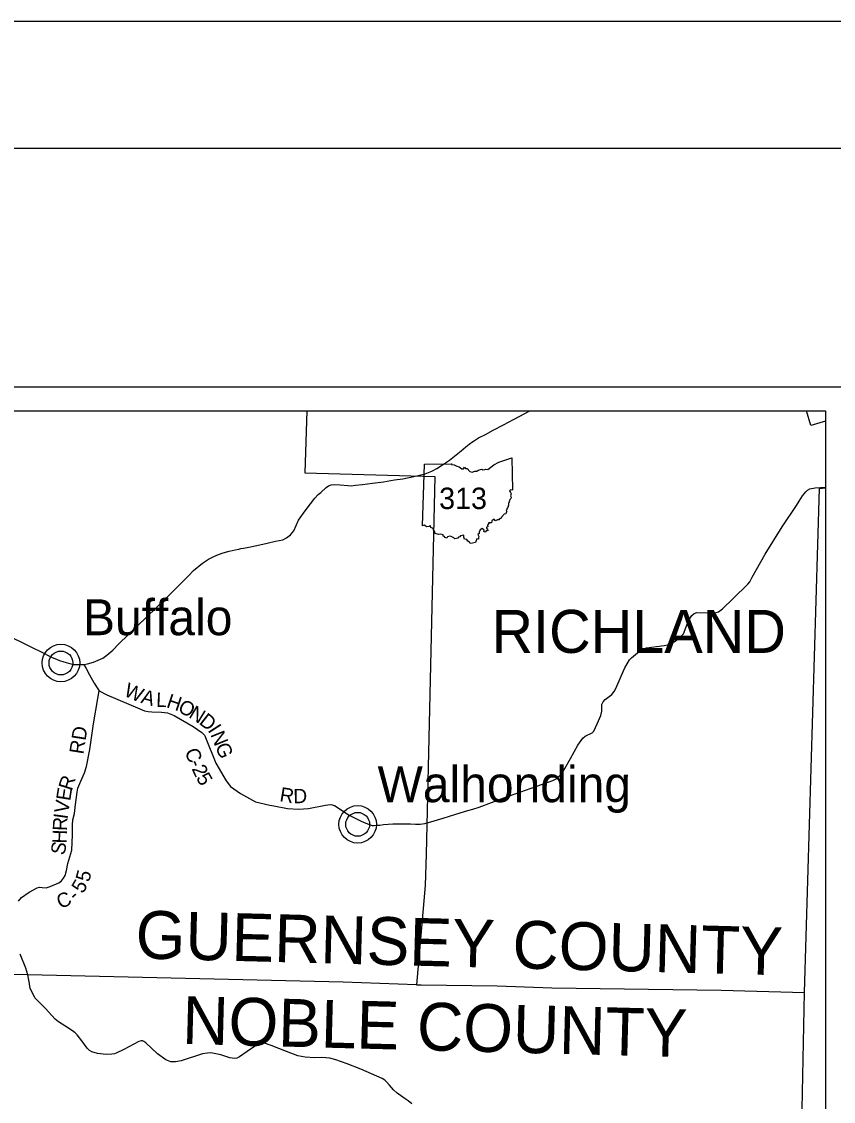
# Model space of a CAD drawing. Extents: x 0 to 34, y 0 to 22.
# Drawn here: x 27.522 to 30.728, y 17.734 to 22 of the extents above; entities that cross this region are included whole.
import ezdxf

# ---------------------------------------------------------------- set-up
doc = ezdxf.new("R2010")
doc.units = 0
for name, color, linetype in [('Default', 7, 'Continuous'), ('GM_X_Corporation', 7, 'Continuous'), ('GM_X_County_Road_Text', 7, 'Continuous'), ('GM_X_State_Route', 7, 'Continuous'), ('GM_X_Township', 7, 'Continuous'), ('GM_X_Township_Text', 7, 'Continuous'), ('GM_X_Unincorporated', 7, 'Continuous'), ('GM_X_Unincorporated_Text', 7, 'Continuous'), ('SH_Border', 7, 'Continuous'), ('SH_Cut_Line', 7, 'Continuous')]:
    doc.layers.add(name, color=color, linetype=linetype)

msp = doc.modelspace()

# ---------------------------------------------------------------- linework, layer by layer
at = {"layer": 'Default'}
for p, q in [((19.8526, 20.4625), (30.697, 20.4625)), ((30.697, 20.4625), (30.697, 9.6182)), ((29.1053, 20.0074), (29.1131, 20.2514))]:
    msp.add_line(p, q, dxfattribs=at)
msp.add_lwpolyline([(19.7581, 20.557), (30.7915, 20.557), (30.7915, 9.5237), (19.7581, 9.5237)], close=True, dxfattribs=at)
for points in [[(29.1131, 20.2514), (29.2213, 20.253), (29.2197, 20.25), (29.2298, 20.2494), (29.2407, 20.2442), (29.2499, 20.2409), (29.261, 20.2332), (29.2678, 20.2332), (29.2706, 20.2396), (29.2757, 20.2347), (29.2819, 20.2338), (29.2924, 20.2221), (29.3012, 20.2196), (29.3116, 20.2236), (29.3193, 20.2243), (29.325, 20.2282), (29.3399, 20.2316), (29.3441, 20.2296), (29.3519, 20.23), (29.3559, 20.2315), (29.3628, 20.2302), (29.3747, 20.2391), (29.3872, 20.2495), (29.4063, 20.2594), (29.4348, 20.2687), (29.4574, 20.2771), (29.4607, 20.1504)], [(29.3034, 18.8884), (29.3285, 18.8962), (29.4266, 18.9332), (29.6197, 19.0014), (29.6357, 19.0103), (29.6547, 19.0287), (29.6678, 19.049), (29.69, 19.0889), (29.7185, 19.1412), (29.7384, 19.1686), (29.7483, 19.1768), (29.7753, 19.1898), (29.7814, 19.197), (29.7956, 19.2263), (29.8092, 19.2591), (29.8139, 19.2757), (29.8133, 19.2931), (29.8141, 19.3015), (29.8187, 19.3128), (29.8271, 19.3214), (29.8431, 19.3333), (29.853, 19.3419), (29.8618, 19.3532), (29.8684, 19.3656), (29.89, 19.4139), (29.9046, 19.4463), (29.9223, 19.4779), (29.9303, 19.4865), (29.9616, 19.5131), (29.973, 19.5201), (29.9904, 19.5256), (30.029, 19.5306), (30.06, 19.5355), (30.0748, 19.5384), (30.0998, 19.5499), (30.1207, 19.5648), (30.1356, 19.5813), (30.1468, 19.6085), (30.1558, 19.6322), (30.164, 19.6452), (30.1692, 19.6533), (30.1776, 19.6619), (30.1882, 19.6652), (30.2588, 19.6638), (30.2744, 19.6678), (30.2896, 19.6801), (30.3323, 19.7206), (30.3906, 19.7775), (30.3983, 19.7869), (30.4071, 19.8054), (30.459, 19.8957), (30.5261, 20.0037), (30.5817, 20.0885), (30.5923, 20.1057), (30.6062, 20.1261), (30.6186, 20.1427), (30.6253, 20.1494), (30.6347, 20.1546), (30.6566, 20.1575), (30.697, 20.1605)], [(29.4607, 20.1504), (29.4574, 20.1487), (29.4522, 20.1495), (29.4487, 20.146), (29.453, 20.14), (29.455, 20.1338), (29.4532, 20.1269), (29.455, 20.1212), (29.4538, 20.1164), (29.4506, 20.1116), (29.4494, 20.1072), (29.4467, 20.1024), (29.4469, 20.0997), (29.4443, 20.0977), (29.4447, 20.0897), (29.4434, 20.0853), (29.4439, 20.0815), (29.4395, 20.0805), (29.4405, 20.0774), (29.4378, 20.075), (29.4384, 20.0708), (29.4353, 20.0681), (29.4383, 20.0629), (29.4359, 20.0612), (29.4339, 20.0547), (29.4284, 20.0534), (29.4174, 20.0416), (29.4135, 20.0371), (29.4092, 20.036), (29.4067, 20.0314), (29.4014, 20.0314), (29.3932, 20.0282), (29.388, 20.0337), (29.3788, 20.0271), (29.3777, 20.0195), (29.3662, 20.0197), (29.3666, 20.0159), (29.364, 20.0148), (29.3616, 20.0109), (29.363, 20.0041), (29.3575, 20.0023), (29.3582, 19.9984), (29.3617, 19.996), (29.3632, 19.9883), (29.3574, 19.9899), (29.3527, 19.9835), (29.3478, 19.985), (29.3494, 19.9904), (29.3411, 19.997), (29.3334, 19.9917), (29.3293, 19.9833), (29.3292, 19.9777), (29.3234, 19.9743), (29.3272, 19.9664), (29.3264, 19.9609), (29.3266, 19.9557), (29.3193, 19.9559), (29.3149, 19.9419)], [(29.3149, 19.9419), (29.3023, 19.9392), (29.2936, 19.9376), (29.2904, 19.944), (29.2842, 19.9474), (29.2801, 19.9537), (29.2711, 19.9546), (29.269, 19.9634), (29.268, 19.9705), (29.2557, 19.9688), (29.2523, 19.9644), (29.2479, 19.9633), (29.2454, 19.9588), (29.2394, 19.9585), (29.233, 19.9564), (29.2288, 19.9607), (29.2184, 19.9651), (29.2137, 19.9673), (29.2038, 19.9638), (29.2018, 19.9597), (29.194, 19.9615), (29.1921, 19.9661), (29.1874, 19.9675), (29.1863, 19.9723), (29.1762, 19.975), (29.1684, 19.9739), (29.1548, 19.9778), (29.1539, 19.9842), (29.1493, 19.992), (29.1469, 19.9974), (29.1383, 20.0015), (29.1365, 20.008), (29.1338, 20.0078), (29.1312, 20.0052), (29.1216, 20.0039), (29.1178, 20.0066), (29.1124, 20.0111), (29.1053, 20.0074)], [(27.7684, 19.4605), (27.7765, 19.4438), (27.7903, 19.4187), (27.8091, 19.3857), (27.8226, 19.3641), (27.8289, 19.3556), (27.859, 19.3407), (27.8931, 19.3258), (27.989, 19.2847), (28.0071, 19.2776), (28.0213, 19.2745), (28.0362, 19.273), (28.0751, 19.272), (28.0985, 19.2695), (28.1249, 19.2592), (28.1993, 19.2153), (28.234, 19.1919), (28.2439, 19.1813), (28.2489, 19.172), (28.2896, 19.0699), (28.3294, 18.9998), (28.3469, 18.9775), (28.3859, 18.9505), (28.4459, 18.9177), (28.5027, 18.9049), (28.5175, 18.9021), (28.5715, 18.8916), (28.6152, 18.889), (28.6552, 18.8918), (28.7219, 18.9044), (28.7312, 18.906), (28.7437, 18.9064), (28.7576, 18.9029), (28.7718, 18.8944), (28.8126, 18.8655), (28.8368, 18.8544), (28.8632, 18.8408), (28.8814, 18.8328), (28.9059, 18.8246), (28.9141, 18.8239), (28.9269, 18.825), (28.9374, 18.825), (28.9511, 18.8279), (28.988, 18.8304), (29.0325, 18.8308), (29.0585, 18.8302), (29.0777, 18.8288), (29.0962, 18.8298), (29.1148, 18.8321), (29.1226, 18.8344), (29.1283, 18.836)], [(27.5096, 18.5246), (27.5222, 18.5392), (27.5522, 18.56), (27.5837, 18.5774), (27.5931, 18.58), (27.6037, 18.5787), (27.6184, 18.5774), (27.6342, 18.5829), (27.6694, 18.5972), (27.6797, 18.605), (27.6877, 18.6155), (27.6935, 18.6264), (27.6998, 18.646), (27.705, 18.6739), (27.7199, 18.726), (27.7231, 18.7873), (27.7231, 18.8271), (27.7247, 18.847), (27.7303, 18.8717), (27.7342, 18.9067), (27.7414, 18.956), (27.7446, 18.9712), (27.7517, 18.9903), (27.7645, 19.0205), (27.7708, 19.0325), (27.7788, 19.0571), (27.7915, 19.1248), (27.8061, 19.2252), (27.8233, 19.3258), (27.8289, 19.3556)], [(29.1283, 18.836), (29.1865, 18.8527), (29.2375, 18.8686), (29.2849, 18.8827), (29.3034, 18.8884)], [(27.5471, 18.2342), (27.5388, 18.2607), (27.5165, 18.3156)], [(29.0634, 17.7248), (29.0488, 17.7363), (29.0364, 17.7441), (29.018, 17.7572), (29.0053, 17.7668), (28.9907, 17.7799), (28.9747, 17.7979), (28.9639, 17.8105), (28.9571, 17.8174), (28.9459, 17.8251), (28.8612, 17.8614), (28.8082, 17.8818), (28.7626, 17.8979), (28.7392, 17.9047), (28.7073, 17.9073), (28.6802, 17.9065), (28.6421, 17.9087), (28.6123, 17.9143), (28.5676, 17.9306), (28.5079, 17.9554), (28.4816, 17.9644), (28.4699, 17.9641), (28.4551, 17.9578), (28.4414, 17.9504), (28.4122, 17.931), (28.3822, 17.9105), (28.3715, 17.9049), (28.3625, 17.9031), (28.3448, 17.906), (28.3094, 17.9177), (28.2895, 17.922), (28.2688, 17.9252), (28.2559, 17.9242), (28.2367, 17.9214), (28.1523, 17.8946), (28.1292, 17.8903), (28.1111, 17.8908), (28.0912, 17.8978), (28.0586, 17.9216), (28.013, 17.9648), (28.0044, 17.971), (27.9995, 17.9733), (27.9942, 17.9737), (27.9851, 17.9711), (27.9252, 17.9388), (27.8956, 17.924), (27.8888, 17.9214), (27.8779, 17.92), (27.856, 17.9198), (27.8221, 17.9236), (27.7995, 17.9294), (27.7905, 17.9348), (27.7804, 17.9444), (27.7596, 17.9726), (27.7409, 17.9966), (27.7335, 18.005), (27.7234, 18.0134), (27.6971, 18.0296), (27.6671, 18.0488), (27.6541, 18.0595), (27.6417, 18.0736), (27.6167, 18.1007), (27.5749, 18.1435), (27.556, 18.1812), (27.5542, 18.1883), (27.5531, 18.1998), (27.5509, 18.2128), (27.5471, 18.2342)]]:
    msp.add_lwpolyline(points, dxfattribs=at)
at = {"layer": 'GM_X_Corporation'}
msp.add_lwpolyline([(30.697, 20.4208), (30.6393, 20.4049), (30.6219, 20.4625)], dxfattribs=at)
at = {"layer": 'GM_X_State_Route'}
for points in [[(28.3879, 19.9177), (28.3977, 19.9195), (28.4199, 19.9239), (28.4509, 19.9307), (28.492, 19.9399), (28.5252, 19.9477), (28.5531, 19.9523), (28.5686, 19.9601), (28.5846, 19.9725), (28.597, 19.988), (28.6149, 20.0304), (28.6413, 20.067), (28.6625, 20.0949), (28.6796, 20.1167), (28.6932, 20.1311), (28.7032, 20.1392), (28.725, 20.1592), (28.7344, 20.1661), (28.7441, 20.1705), (28.7581, 20.1711), (28.7801, 20.1699), (28.8108, 20.167), (28.8241, 20.1665), (28.84, 20.1686), (28.8683, 20.1718), (28.9076, 20.1758), (28.9511, 20.1811), (28.9943, 20.1891), (29.0272, 20.1937), (29.0711, 20.2022), (29.1153, 20.2137), (29.1416, 20.2244), (29.1623, 20.2349), (29.1885, 20.2513), (29.2121, 20.2676), (29.2382, 20.2889), (29.2577, 20.3047), (29.2759, 20.3202), (29.289, 20.331), (29.3038, 20.341), (29.3062, 20.3427), (29.3269, 20.3552), (29.3539, 20.3689), (29.3839, 20.3853), (29.4252, 20.4068), (29.4646, 20.4283), (29.5093, 20.4514), (29.5292, 20.4625)], [(27.6534, 19.4834), (27.6713, 19.476), (27.6887, 19.4705), (27.7073, 19.4653), (27.7269, 19.4601), (27.751, 19.4601), (27.7684, 19.4605), (27.7825, 19.4626), (27.8063, 19.4687), (27.825, 19.4768), (27.8424, 19.4857), (27.8587, 19.497), (27.8824, 19.5172), (27.906, 19.542), (28.0905, 19.7197), (28.1464, 19.776), (28.1805, 19.8102), (28.2006, 19.8314), (28.2368, 19.8603), (28.2606, 19.8758), (28.2807, 19.8862), (28.2993, 19.8944), (28.3185, 19.9006), (28.3417, 19.9079), (28.3652, 19.9134), (28.3804, 19.9163), (28.3879, 19.9177)], [(27.4673, 19.5756), (27.4916, 19.5625), (27.5167, 19.5504), (27.5272, 19.5453), (27.5686, 19.5252), (27.5962, 19.5118), (27.6423, 19.4879), (27.6534, 19.4834)]]:
    msp.add_lwpolyline(points, dxfattribs=at)
at = {"layer": 'GM_X_Township'}
for p, q in [((28.6479, 20.4625), (28.6401, 20.2176)), ((28.6401, 20.2176), (29.1534, 20.2032)), ((29.1534, 20.2032), (29.1192, 18.7104)), ((30.6135, 18.1642), (30.6737, 20.1555)), ((30.6737, 20.1555), (30.697, 20.1586)), ((29.1192, 18.7104), (29.1158, 18.5864)), ((29.1158, 18.5864), (29.081, 18.1946)), ((27.5471, 18.2342), (27.1122, 18.2431)), ((28.7916, 18.2049), (27.5471, 18.2342)), ((29.081, 18.1946), (28.7916, 18.2049)), ((29.081, 18.1946), (29.1005, 18.1942)), ((29.081, 18.1946), (29.1005, 18.1942)), ((29.1005, 18.1942), (29.4003, 18.1902)), ((29.4003, 18.1902), (29.6157, 18.1824)), ((29.4003, 18.1902), (29.6157, 18.1824)), ((29.6157, 18.1824), (30.2842, 18.1734)), ((29.6157, 18.1824), (30.2842, 18.1734)), ((30.2842, 18.1734), (30.6135, 18.1642)), ((30.2842, 18.1734), (30.6135, 18.1642)), ((30.5368, 14.1558), (30.6135, 18.1642))]:
    msp.add_line(p, q, dxfattribs=at)
at = {"layer": 'GM_X_Unincorporated'}
for centre, radius in [((27.6773, 19.466), 0.0742), ((27.6773, 19.466), 0.0471), ((28.8492, 18.8286), 0.0742), ((28.8492, 18.8286), 0.0471)]:
    msp.add_circle(centre, radius, dxfattribs=at)
at = {"layer": 'SH_Border'}
msp.add_lwpolyline([(1.5, 21.5), (33.5, 21.5), (33.5, 0.5), (1.5, 0.5)], close=True, dxfattribs=at)
at = {"layer": 'SH_Cut_Line'}
msp.add_lwpolyline([(0, 0), (34, 0), (34, 22), (0, 22)], close=True, dxfattribs=at)

# ---------------------------------------------------------------- texts
at = {"layer": 'Default'}
msp.add_text('313', height=0.08462, dxfattribs=at).set_placement((29.171, 20.0742))
at = {"layer": 'GM_X_County_Road_Text'}
for s, rotation, p in [('W', 336.5322, (27.9222, 19.338)), ('A', 344.0822, (27.9901, 19.3091)), ('L', 357.6294, (28.0525, 19.2931)), ('H', 341.3185, (28.0907, 19.2921)), ('O', 330.1652, (28.1353, 19.2773)), ('N', 328.7101, (28.1783, 19.2527)), ('D', 321.9148, (28.2195, 19.2278)), ('RD', 81.0031, (27.7658, 19.1032)), ('I', 302.7613, (28.2554, 19.2007)), ('N', 292.2086, (28.2667, 19.1835)), ('C', 291.4274, (28.1651, 19.1169)), ('G', 292.3249, (28.2856, 19.1372)), ('-', 292.4657, (28.1826, 19.0725)), ('2', 294.9234, (28.1925, 19.0486)), ('5', 299.6253, (28.2096, 19.0124)), ('R', 72.1902, (27.7198, 18.9586)), ('E', 81.0886, (27.7138, 18.919)), ('R', 350.6538, (28.5386, 18.9202)), ('D', 0.8434, (28.5953, 18.9118)), ('V', 81.4147, (27.7063, 18.8697)), ('I', 82.0278, (27.7031, 18.8468)), ('R', 87.6927, (27.7014, 18.8018)), ('H', 88.1853, (27.6998, 18.752)), ('S', 78.3695, (27.6909, 18.704)), ('5', 75.0386, (27.7885, 18.5979)), ('5', 58.959, (27.7637, 18.552)), ('C', 23.1227, (27.6747, 18.4933)), ('-', 41.4708, (27.7343, 18.5221))]:
    msp.add_text(s, height=0.0567, rotation=rotation, dxfattribs=at).set_placement(p)
at = {"layer": 'GM_X_Township_Text'}
msp.add_text('RICHLAND', height=0.1701, rotation=0, dxfattribs=at).set_placement((29.3777, 19.5058))
at = {"layer": 'GM_X_Unincorporated_Text'}
for s, height, rotation, p in [('Buffalo', 0.14175, 0, (27.7645, 19.5758)), ('Walhonding', 0.14175, 0, (28.9277, 18.9161)), ('GUERNSEY COUNTY', 0.189, 358.4869, (27.9704, 18.2994)), ('NOBLE COUNTY', 0.189, 358.4869, (28.1546, 17.9613))]:
    msp.add_text(s, height=height, rotation=rotation, dxfattribs=at).set_placement(p)

doc.saveas('drawing.dxf')
